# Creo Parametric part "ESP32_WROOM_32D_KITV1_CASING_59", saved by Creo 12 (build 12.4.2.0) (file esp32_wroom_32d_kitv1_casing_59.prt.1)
Units: Custom; MM, KILOGRAM, SECS

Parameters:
  PTC_WM_ITERATION = "0"
  PTC_WM_VERSION = "-.0"
  PTC_WM_LIFECYCLE_STATE = "In Work"
  PTC_WM_LIFECYCLE = "MO_CADDocument"
  PTC_WM_CREATED_BY = "Maximilian Roepper (Z0017RMS: MO)"
  PTC_WM_CREATED_ON = "18-Sep-26 11:36:42 AM"
  PTC_WM_MODIFIED_BY = "Maximilian Roepper (Z0017RMS: MO)"
  PTC_WM_MODIFIED_ON = "18-Sep-26 11:36:46 AM"
  PDMLINKNUMBER = "PDM000071455323"
  PTC_WM_NAME = "esp32_wroom_32d_kitv1_casing_59.prt"
  PTC_WM_NUMBER = "PDM000071455323"

Other parameters: WEIGHT, WEIGHT_FACTOR, WEIGHT_ADD, _MASS_TEMP, _DIFF_TEMP, MC_ERRORS, SUPPLIER

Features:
  1. coordinate system
  2. datum plane "PRT_YZ"
  3. datum plane "PRT_XY"
  4. datum plane "PRT_XZ"
  5. coordinate system
  6. datum axis
  7. datum axis
  8. datum axis
  9. coordinate system
  10. imported feature
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
Other named items: PRT, SIEMENS_MO, DRW_VIEW_ORG, PRT_X, PRT_Y, PRT_Z, CS0, ROUGH_GROB

Layers: 00_STD_CSYS-KSYS, 01_STD_PLANES-EBENEN, 02_STD_AXES-ACHSEN, 03_STD_CSYS-KSYS, 24_IMPORT_FEAT-IMPORT_KE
